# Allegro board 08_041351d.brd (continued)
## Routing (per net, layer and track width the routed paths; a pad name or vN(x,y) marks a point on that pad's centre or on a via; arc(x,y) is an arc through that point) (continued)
UNNAMED_10_RES_I39_N2: length 2.7
  TOP w0.14: v1(77.27,50.4) 77.27,51.04 Y4.1
  BOTTOM w0.14: R55.2 R54.2 77.14,50.53 v1(77.27,50.4)
UNNAMED_13_CN100PODDEVEN_I16_N4: length 6.8
  BOTTOM w0.089: JP3.2 16.31,31.52 16.18,31.64 14.78,31.64 14.4,32.02 14.4,32.49 14.28,32.62 14.28,33.81 14.03,34.06 13.57,34.06 13.29,33.77 JX3.58
UNNAMED_13_CN100PODDEVEN_I16_N5: length 6.8
  BOTTOM w0.089: JP4.2 16.31,31.99 16.18,31.86 14.87,31.86 14.62,32.11 14.62,32.58 14.49,32.71 14.49,33.9 14.12,34.27 13.51,34.27 13.21,34.57 JX3.60
UNNAMED_13_CN100PODDEVEN_I17_N4: length 4.9
  BOTTOM w0.089: JX3.57 7.32,33.77 7.04,34.06 6.85,34.06 6.22,33.42 4.79,33.42 4.62,33.25 JP1.2
UNNAMED_13_CN100PODDEVEN_I17_N5: length 4.8
  BOTTOM w0.089: JP2.2 4.62,33.76 4.75,33.64 6.13,33.64 6.76,34.27 7.04,34.27 7.34,34.57 JX3.59
USB_ID: length 24.4
  TOP w0.14: U15.23 v1(19.63,51.69)
  L6_SIGNAL w0.095: v1(19.63,51.69) 17.83,49.89 17.83,40.68 13.01,35.86 9.76,35.86 v1(9.45,36.17)
  BOTTOM w0.14: JX3.63 v1(9.45,36.17)
USB_OTG_CPEN: length 21.1
  TOP w0.14: U15.17 v1(19,54.69)
  L6_SIGNAL w0.095: v1(13.91,38.57) 13.91,39.37 16.63,42.08 16.63,52.31 v1(19,54.69)
  BOTTOM w0.14: JX3.70 v1(13.91,38.57)
USB_OTG_N: length 32.1
  TOP w0.089: 16.5,52.64 U16.6 ; 16.5,52.64 16.84,52.98 18.18,52.98 19.03,53.83 19.76,53.83 19.9,53.69 U15.19 ; 16.5,52.64 16.15,52.98 13.86,52.98 12.59,51.71 9.23,51.71 8.51,52.43 v1(8.31,52.43)
  L6_SIGNAL w0.089: v1(6.66,38.59) 6.91,38.34 7.55,38.34 8.69,39.48 8.69,51.67 8.82,51.8 8.82,52.18 8.56,52.43 v1(8.31,52.43)
  BOTTOM w0.089: v1(6.66,38.59) 6.95,38.3 7.13,38.3 7.4,38.57 JX3.69
USB_OTG_P: length 32.4
  TOP w0.089: 16.5,53.39 U16.1 ; 16.5,53.39 16.69,53.19 18.09,53.19 18.94,54.05 19.76,54.05 19.9,54.19 U15.18 ; 16.5,53.39 16.3,53.19 13.77,53.19 12.5,51.92 9.32,51.92 8.69,52.56 v1(8.69,52.81)
  L6_SIGNAL w0.089: v1(8.69,52.81) 8.69,52.66 9.07,52.28 9.07,51.69 8.94,51.57 8.94,39.37 7.65,38.08 v1(6.66,38.08)
  BOTTOM w0.089: JX3.67 7.35,37.77 7.04,38.08 v1(6.66,38.08)
USB_VBUS_OTG: length 19.8
  TOP w0.14: U15.22 19.11,52.19 v1(19.1,52.18)
  L6_SIGNAL w0.095: v1(19.1,52.18) 18.72,52.18 17.2,50.65 17.2,40.62 14.4,37.83 v1(13.9,37.83)
  BOTTOM w0.14: JX3.68 13.84,37.77 v1(13.9,37.83)
V_0_N: length 36
  TOP w0.127: U1.K9 v1(29.94,32.19)
  L16_SIGNAL w0.095: v1(29.94,32.19) 29.08,32.19 28.65,31.76 21.02,31.76 20.8,31.53 20.8,31.52 20.12,30.84 20.12,23.1 12.88,15.86 11.99,15.86 9.7,13.57 v1(9.7,12.17)
  BOTTOM w0.14: JX3.3 v1(9.7,12.17)
V_0_P: length 35
  TOP w0.127: U1.L10 v1(28.34,31.39)
  L16_SIGNAL w0.095: v1(10.59,11.37) 12.08,11.37 15.42,14.71 15.42,16.24 20.5,21.32 20.5,29.95 21.39,30.84 27.1,30.84 27.31,31.05 27.68,31.05 28.02,31.39 v1(28.34,31.39)
  BOTTOM w0.14: v1(10.59,11.37) JX3.1
VTT_0P75: length 21
  TOP w0.305: R150.2 v1(45.2,49.57)
  TOP w0.356: R148.2 v1(45.77,48.24) ; R159.2 v1(46.66,42.78) ; R138.2 v1(46.66,45.83) ; R146.2 45.19,48.99 45.2,49.13 v1(45.2,49.57) ; R156.2 v1(46.66,42.02) ; R149.2 v1(45.77,46.72) ; R143.2 v1(51.61,46.97) ; R140.2 v1(51.61,45.96) ; R152.2 v1(40.06,44.56) ; R145.2 v1(49.01,49.57) ; R155.2 v1(46.66,43.54) ; R137.2 v1(45.77,47.48) ; R162.2 v1(39.68,42.65) ; R144.2 v1(42.15,49.57) ; R154.2 R136.2 v1(46.66,45.07) ; R139.2 v1(40.06,45.45) ; R153.2 v1(51.61,45.07) ; R141.2 v1(40.06,46.34) ; R163.2 v1(40.18,43.54) ; R147.2 v1(51.23,44.05) ; R151.2 v1(47.49,49.57)
  TOP w0.406: R160.2 v1(51.36,40.62)
  BOTTOM w0.203: U14.3 48.52,59.42
  BOTTOM w0.305: U24.2 76.63,41.6 76.13,41.1 76.13,39.8
  BOTTOM w0.381: C101.1 52.25,47.61 v1(51.61,46.97)
  BOTTOM w0.508: v1(51.74,59.54) C80.1 50.6,59.54 50.47,59.67 v1(50.34,59.67) 50.22,59.67 50.09,59.54 R161.1
  BOTTOM w0.635: 76.13,39.8 v1(76.13,37.83) v1(76.71,37.83)
  vias: v1(49.58,57.26) v1(50.22,57.26) v1(51.61,57.26)
VTTVREF: length 133.5
  TOP w0.127: U1.H6 v1(31.54,34.59) ; U1.P6 v1(25.94,34.59)
  TOP w0.254: C123.2 48.76,27.56 v1(48.83,27.63) ; v1(46.79,44.3) 47.04,44.56 C122.2 ; C102.1 42.4,40.3 v1(42.43,40.33) ; C103.1 42.4,23.54 v1(42.43,23.57)
  TOP w0.508: v1(46.34,58.27) 46.03,58.59 C81.1
  L3_SIGNAL w0.254: v1(46.79,44.3) 45.9,44.3 45.26,43.67 45.26,41.76 44.63,41.13 42.72,41.13 42.43,40.83 v1(42.43,40.33)
  L6_SIGNAL w0.254: v1(74.35,37.55) 74.35,38.56 74.09,38.82 74.09,39.22 75.11,40.24 75.11,43.48 74.54,44.05 74.54,46.15 72.95,47.73 72.95,49.13 71.17,50.91 68,50.91 62.41,56.5 49.2,56.5 47.42,58.27 v1(46.34,58.27) 45.85,57.78 45.85,52.28 45.9,52.23 45.9,49.38 45.26,48.75 45.26,45.19 46.15,44.3 v1(46.79,44.3)
  L9_POWER w0.203: v1(31.54,34.59) 31.93,34.98 31.93,37.19 32.13,37.4 32.5,37.4 32.73,37.63 32.73,37.99 32.93,38.2 37.9,38.2
  L9_POWER w0.254: 37.9,38.2 37.91,38.21 39.17,38.21 41.29,40.33 v1(42.43,40.33)
  L15_SIGNAL w0.203: v1(31.54,34.59) 31.14,34.2 26.57,34.2 26.18,34.59 v1(25.94,34.59)
  L16_SIGNAL w0.254: v1(46.79,44.3) 46.41,44.3 46.03,43.92 46.03,41.76 46.41,41.38 46.41,28.81 47.42,27.79 48.66,27.79 v1(48.83,27.63) 48.36,27.16 47.8,27.16 47.17,26.52 47.17,25.76 46.03,24.62 43.99,24.62 43.74,24.87 42.85,24.87 42.43,24.45 v1(42.43,23.57)
  BOTTOM w0.178: 47.83,44.3 47.81,44.3 47.79,44.32 47.46,44.32 47.44,44.3 47.43,44.3
  BOTTOM w0.203: 47.43,44.3 v1(46.79,44.3) ; C84.1 v1(46.34,58.27) 46.34,58.41 46.14,58.62 U14.6 ; U2.H1 v1(42.43,23.57) ; U3.M8 48.26,44.1 48.19,44.1 47.98,44.3 47.83,44.3
  BOTTOM w0.254: v1(74.35,37.55) 75.31,38.51 75.31,41 76.13,41.82 U24.3 ; U2.M8 48.83,27.57 v1(48.83,27.63) ; U3.H1 v1(42.43,40.33)
  BOTTOM w0.305: v1(31.54,34.59) 31.66,34.46 C77.1 ; C76.1 26.06,34.46 v1(25.94,34.59)
XTAL_N: length 3.4
  TOP w0.127: U17.M12 69.6,34.75 v1(69.22,35.14)
  BOTTOM w0.14: v1(69.22,35.14) 70.18,35.14 C165.1 C216.2

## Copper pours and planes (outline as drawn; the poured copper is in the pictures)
1.0V on TOP: 36.37,12.94 36.37,15.22 37.64,15.22 37.64,14.01 38.15,14.01 38.15,12.94
1.0V on TOP: 12.37,7.22 12.37,0.49 9.45,0.49 9.45,7.22
1.0V on TOP: 57.08,1.25 56.57,1.76 56.57,2.14 57.08,2.65 57.08,5.19 58.47,5.19 58.47,1.25
1.0V on BOTTOM: 9.45,7.22 9.45,0.49 12.37,0.49 12.37,7.22
1.0V on BOTTOM: 56.31,1.38 56.31,5.19 58.47,5.19 58.47,1.38
1.0V on L3_SIGNAL: 57.08,5.95 57.08,11.41 37.39,11.41 36.63,12.17 36.63,12.81 35.99,13.44 35.99,14.46 63.3,14.46 64.31,13.44 64.31,5.32 59.36,0.36 9.32,0.36 9.32,7.35 14.78,7.35 16.69,5.44 27.48,5.44 28.25,4.68 33.33,4.68 34.6,3.41 36.12,3.41 36.37,3.66 52.12,3.66 52.38,3.41 54.54,3.41
1.8V on TOP: 58.98,12.3 60.89,12.3 60.89,13.32 60.38,13.32 60.38,15.35 58.6,15.35 57.33,14.21 56.44,14.21 56.44,12.05 55.68,11.41 55.68,11.03 57.71,11.03
1.8V on TOP: 78.03,5.32 77.14,6.2 77.14,6.97 76.63,7.47 76.63,8.49 76.89,8.74 77.65,8.74 77.65,7.47 78.41,6.71 81.33,6.71 81.71,6.33 81.71,5.44 81.46,5.19 80.57,5.19 80.19,4.81 80.19,2.9 79.94,2.65 78.54,2.65 78.03,3.16
1.8V on TOP: 28.75,5.44 28.75,4.3 30.53,4.3 30.53,5.44
1.8V on TOP: 11.74,11.54 11.74,10.65 15.29,10.65 15.29,12.05 15.04,12.3 15.04,13.32 13.51,13.32
1.8V on L9_POWER: 89.32,9.45 89.29,9.46 91.24,11.41 91.24,42.15 87.17,46.21 75.49,46.21 74.22,47.48 74.22,53.19 74.35,53.32 95.81,53.32 99.11,50.02 99.11,8.11 92.64,1.63 15.29,1.63 11.79,5.14 11.79,12.1 13.39,13.7 22.28,13.7 28.63,7.35 31.55,7.35 32.18,6.71 63.17,6.71 63.17,10.4 61.52,12.05 58.85,12.05 58.85,16.36 60,17.51 67.24,17.51 67.87,17 70.28,14.59 71.17,14.08 73.33,14.08 74.98,12.17 75.11,12.05 75.11,8.62 88.44,8.62 89.13,9.3 89.14,9.27 89.16,9.24 89.19,9.21 89.27,9.17 89.35,9.21 89.38,9.24 89.41,9.32 89.38,9.39 89.35,9.43 ; 15 cut-outs
1.35V on TOP: 62.79,16.11 62.79,13.95 66.73,13.95 66.73,16.11
1.35V on BOTTOM: 65.71,17.38 65.71,13.44 62.79,13.44 61.39,14.97 61.39,17.25 61.52,17.38
1.35V on L10_POWER: 50.85,1.51 50.85,4.81 51.49,5.44 52,5.44 52.25,5.19 52.25,3.54 52.88,2.9 57.08,2.9 58.73,4.55 58.73,15.86 60.12,17.25 64.31,17.25 66.22,15.35 66.22,12.43 64.44,10.65 62.92,10.65 61.65,9.38 61.65,2.65 59.74,0.74 51.61,0.74
3.3V on TOP: 37.64,53.32 35.8,53.32 35.42,53.7 35.42,56.43 36.56,56.43 36.56,55.1 36.95,54.72 37.64,54.72
3.3V on L10_POWER: 9.45,21.19 11.99,18.65 11.99,17.76 11.23,17 0.69,17 0.56,17.13 0.56,50.78 11.1,61.32 37.01,61.32 37.9,60.43 37.9,53.83 37.39,53.32 36.37,53.32 32.06,57.64 25.07,57.64 24.44,58.27 12.5,58.27 10.09,55.86 10.09,32.49 7.93,30.33 5.77,30.33 5.13,29.7 5.13,28.81 5.77,28.18 8.18,28.18 9.45,26.91
3.3V on L10_POWER: 70.41,61.2 70.41,42.4 78.16,42.4 81.59,45.83 81.59,61.2 ; 4 cut-outs
3.3V on L15_SIGNAL: 11.99,18.9 10.34,18.9 9.83,18.4 9.83,18.02 12.37,15.48 17.71,15.48 20.37,18.14 25.33,18.14 25.83,17.63 25.83,15.09 26.6,14.33 26.6,12.68 30.02,9.25 30.02,7.6 30.66,6.97 31.04,6.97 31.55,7.47 31.55,10.78 26.6,15.73 26.6,18.14 25.33,19.41 19.86,19.41 17.96,17.51 13.39,17.51
3.3V on L15_SIGNAL: 34.98,53.64 36.82,53.64 36.82,55.54 37.33,56.05 78.96,56.05 81.71,58.81 81.71,59.67 33.07,59.67 32.31,58.91 32.31,57.77 32.69,57.39 33.96,57.39 34.6,56.75 34.6,54.02
GND on TOP: 58.73,9.13 60.25,9.13 61.01,8.36 61.01,5.32 60.63,4.93 60.63,4.3 60.25,3.92 58.98,3.92 58.85,4.05 58.85,8.11 58.73,8.24
GND on TOP: 19.61,8.11 19.74,7.98 20.63,7.98 21.39,8.74 21.39,9 19.74,9 19.61,8.87
GND on TOP: 38.66,18.14 38.66,16.11 40.69,16.11 40.69,18.14
GND on TOP: 74.35,12.68 74.35,10.9 73.84,10.4 73.84,9.38 74.73,8.49 75.62,8.49 76.25,9.13 76.25,11.92 75.49,12.68
GND on TOP: 37.2,55.23 38.22,55.23 38.22,51.99 39.87,51.99 39.87,54.97 38.41,56.43 37.2,56.43
GND on TOP: 17.9,59.1 18.98,59.1 19.48,58.59 20.56,58.59 20.56,60.24 17.9,60.24
GND on TOP: 66.09,6.71 67.81,6.71 67.81,10.27 66.09,10.27
GND on TOP: outline of 104 points within 62.6,10.19 98.91,54.24 ; 21 cut-outs
GND on BOTTOM: 38.15,54.27 38.15,52.24 39.99,52.24 39.99,54.27
GND on BOTTOM: 60.38,24.62 60.38,30.59 61.14,30.59 61.14,31.35 61.71,31.35 61.71,32.24 61.46,32.24 61.46,34.02 60.38,34.02 60.38,34.53 66.92,34.53 66.92,34.21 67.55,34.21 67.55,34.53 70.16,34.53 70.16,24.62 ; 3 cut-outs
GND on BOTTOM: 66.16,7.86 67.43,7.86 67.43,9.7 66.35,9.7 66.16,9.51
GND on BOTTOM: 65.46,2.84 66.47,2.84 66.73,3.09 69.2,3.09 69.39,2.9 70.47,2.9 70.47,3.79 68.95,5.32 65.46,5.32
GND on BOTTOM: 60.69,24.05 60.69,19.48 60.76,19.41 59.55,19.41 59.55,23.86 59.74,24.05
GND on BOTTOM: 19.36,58.72 21.45,58.72 21.45,60.18 19.36,60.18
GND on BOTTOM: 83.49,24.43 83.81,24.11 83.81,22.97 84.82,22.97 84.82,26.71 84.76,26.78 84.38,26.78 83.49,25.89
GND on BOTTOM: 73.33,31.67 73.33,30.33 74.73,30.33 74.98,30.59 76.19,30.59 76.19,31.67
GND on L2_GROUND: 3.74,0.62 2.34,1 1.2,2.01 0.69,3.16 0.69,58.27 0.94,59.54 1.58,60.43 2.59,61.2 3.74,61.32 96.7,61.32 97.59,61.2 98.6,60.43 99.11,59.67 99.37,58.66 99.37,3.41 99.11,2.39 98.6,1.51 97.59,0.87 96.45,0.62 ; 15 cut-outs
GND on L3_SIGNAL: 89.84,10.27 85.65,14.46 69.55,14.46 69.55,17.81 66.17,17.81 63.68,20.3 63.68,23.73 65.2,25.25 65.2,25.76 65.61,26.17 68.89,26.17 68.89,31.6 68.38,32.11 68.38,34.22 67.92,34.22 67.74,34.4 67.74,44.61 80.06,44.61 85.78,50.32 85.78,54.24 98.68,54.24 98.91,54.01 98.91,10.65 98.53,10.27
GND on L5_GROUND, L14_GROUND, L17_GROUND: 3.74,0.62 2.34,1 1.2,2.01 0.69,3.16 0.69,58.27 0.94,59.54 1.58,60.43 2.59,61.2 3.74,61.32 96.7,61.32 97.59,61.2 98.6,60.43 99.11,59.67 99.37,58.66 99.37,3.41 99.11,2.39 98.6,1.51 97.59,0.87 96.45,0.62 ; 2 cut-outs
GND on L8_GROUND, L11_GROUND: 3.74,0.62 2.21,1 1.07,2.14 0.69,3.28 0.69,58.91 1.32,60.31 2.34,61.2 3.74,61.32 96.57,61.32 97.59,61.2 98.6,60.43 99.11,59.67 99.37,58.53 99.37,3.41 99.11,2.39 98.6,1.51 97.59,0.87 96.45,0.62 ; 2 cut-outs
VCC-1P35 on TOP: 52.91,57.66 52.91,59.65 52.48,60.08 47.6,60.08 47.6,61.5 55.07,61.5 55.07,57.66 ; 1 cut-out
VCC-1P35 on BOTTOM: 55.93,15.09 56.44,14.59 59.87,14.59 60.5,15.22 60.5,16.24 60.25,16.49 55.93,16.49
VCC-1P35 on BOTTOM: 47.55,61.45 47.55,60.18 48.44,60.18 48.44,61.45
VCC-1P35 on L9_POWER: 41.33,18.27 41.33,39.48 41.2,39.48 41.2,48.75 41.45,49 42.09,49 43.11,47.99 43.11,43.16 45.14,41.13 47.55,41.13 47.8,41.38 47.8,46.08 48.19,46.46 48.95,46.46 49.46,46.97 49.96,46.97 50.34,46.59 50.34,39.99 50.6,39.73 51.61,39.73 52.38,40.49 52.38,45.83 52.63,46.08 52.63,49.26 52.38,49.51 52.38,59.42 52.76,59.8 54.28,59.8 58.35,55.73 58.35,37.7 53.14,32.49 53.14,23.86 51.36,22.08 51.36,18.78 50.09,17.51 42.09,17.51
VCC-3P3V on TOP: 21.19,58.66 21.19,60.5 24.18,60.5 24.18,58.66
VCC-3P3V on L3_SIGNAL: 12.75,61.45 46.03,61.45 46.03,60.43 45.14,59.54 26.34,59.54 25.2,58.4 17.07,58.4 16.18,57.51 13.39,57.51 12.63,56.75 12.63,54.97 11.74,54.08 11.36,54.08 10.97,54.46 10.97,59.67
VCC-3P3V-IO on L9_POWER: 0.69,7.35 0.69,41 6.53,46.84 12.63,46.84 25.33,59.54 30.15,59.54 35.87,53.83 35.87,48.5 31.04,43.67 31.04,34.91 30.41,34.27 23.93,34.27 23.48,34.34 22.4,35.41 22.4,40.11 20.63,41.89 12.5,41.89 6.91,36.3 6.91,23.48 4.24,23.48 4.24,18.4 4.62,18.02 7.8,18.02 8.18,17.63 8.18,7.35
VCC-BRAM on BOTTOM: 54.41,4.3 54.41,0.87 55.42,0.87 55.42,4.55 54.66,4.55
VCC-BRAM on L9_POWER: 37.01,31.86 31.42,31.86 30.91,31.35 30.91,30.72 32.69,28.94 36.76,28.94 37.39,28.3 37.39,16.49 38.79,15.09 51.61,15.09 55.17,18.65 55.17,21.06 54.41,21.83 52.38,21.83 52,21.44 52,18.27 50.73,17 41.84,17 40.69,18.14 40.69,28.18
VCC-BRAM on L10_POWER: 54.41,3.28 54.41,6.33 55.3,7.22 55.3,10.01 54.54,10.78 53.39,10.78 53.39,21.19 56.69,21.19 58.35,19.54 58.35,4.93 56.69,3.28
VCC-BRAM on L16_SIGNAL: 54.22,3.41 55.11,3.41 55.55,3.85 55.55,4.68 54.54,5.7 54.47,5.7 54.03,5.25 54.03,3.6
VCCINT-1P0V on TOP: 25.33,14.97 25.33,19.16 26.34,19.16 27.99,20.81 29.52,20.81 29.52,19.41 27.87,19.41 27.61,19.16 27.61,17.51 37.64,17.51 37.64,15.98 29.9,15.98 29.9,14.97
VCCINT-1P0V on L9_POWER: 24.94,29.7 24.94,27.54 28.25,27.54 28.25,21.7 27.36,20.81 27.36,19.03 28.25,18.14 28.25,16.62 28.75,16.11 36.25,16.11 36.88,16.75 36.88,27.92 36.37,28.43 32.56,28.43 30.02,30.97 25.83,30.97
VCCO-DDR on TOP: 46.92,1.38 46.92,3.03 47.17,3.28 48.44,3.28 48.69,3.54 48.69,5.06 48.95,5.32 49.46,5.32 49.71,5.06 49.71,1.63 49.2,1.12 47.17,1.12
VCCO-DDR on L10_POWER: 50.09,29.06 48.44,34.4 42.98,36.05 38.79,36.05 37.9,35.16 35.99,35.16 35.61,34.78 23.04,34.78 20.75,37.07 20.75,40.11 22.79,42.15 23.29,42.15 23.67,41.76 23.67,41.38 24.06,41 25.33,41 25.58,41.26 25.58,41.89 25.83,42.15 26.09,42.15 26.34,41.89 26.34,41.38 26.72,41 30.28,41 31.68,42.4 35.1,42.4 35.49,42.02 35.49,41.38 35.74,41.13 36.5,41.13 36.88,41.64 36.88,42.15 37.14,42.4 54.66,42.4 54.66,23.35 52.88,21.57 52.88,10.78 52.25,10.14 52.25,6.84 50.47,5.06 50.47,4.3 49.96,3.79 49.2,3.79 49.2,8.74 50.09,9.89
VCCPCOM-1P8V on TOP: 17.93,58.59 18.91,58.59 19.31,58.2 23.9,58.2 24.08,58.02 24.08,56.42 23.83,56.17 23.8,56.01 23.52,56.01 23.5,56.12 23.14,56.47 22.73,56.47 22.38,56.12 22.3,56.01 21.87,56.01 20.82,57.07 18.45,57.07 17.93,57.59
VCCPCOM-1P8V on TOP: 25.07,55.61 25.07,54.85 25.33,54.59 25.83,54.59 26.34,55.1 26.34,55.99 26.21,56.12 25.58,56.12
VCCPCOM-1P8V on TOP: 14.53,38.08 14.53,35.48 18.21,35.48 18.21,38.08
VCCPCOM-1P8V on BOTTOM: 16.56,17.76 14.4,17.76 14.02,17.38 14.02,15.73 14.28,15.48 14.66,15.48 15.17,15.98 15.17,16.49 15.29,16.62 16.44,16.62 16.56,16.75
VCCPCOM-1P8V on BOTTOM: 61.14,43.8 61.14,48.62 62.66,48.62 62.66,46.59 63.68,46.59 63.68,43.8
VCCPCOM-1P8V on L10_POWER: 65.9,42.84 37.45,42.84 36.76,42.15 36.76,41.76 36.37,41.38 36.12,41.38 35.87,41.64 35.87,42.27 35.36,42.78 31.29,42.78 30.02,41.38 27.1,41.38 26.72,41.76 26.72,42.15 26.34,42.53 25.58,42.53 25.33,42.27 25.33,41.51 25.2,41.38 24.31,41.38 24.06,41.64 24.06,42.02 23.55,42.53 22.53,42.53 20.25,40.24 20.25,36.81 22.79,34.27 35.74,34.27 36.25,34.78 37.01,34.78 38.91,32.87 38.91,31.6 39.93,30.59 43.36,30.59 44.38,29.57 44.38,14.08 45.01,13.44 45.01,9 45.52,8.49 47.93,8.49 48.69,7.73 48.69,2.52 48.19,2.01 9.96,2.01 6.78,1.89 1.45,7.22 1.45,16.11 11.23,16.11 12.5,17.38 12.5,18.9 9.96,21.44 9.96,24.11 10.09,24.24 10.09,25.51 9.96,25.64 9.96,27.03 8.31,28.68 6.02,28.68 5.64,29.06 5.64,29.45 6.02,29.83 8.31,29.83 10.85,32.37 10.85,55.86 12.75,57.77 24.18,57.77 25.07,56.88 31.8,56.88 35.74,52.94 37.64,52.94 43.49,58.78 47.8,58.78 50.47,61.45 69.52,61.45 69.78,61.2 69.78,46.72 ; 8 cut-outs
VCCPINT-1P0V on TOP: 55.68,8.36 55.68,6.46 56.69,6.46 57.2,5.95 57.96,5.95 58.35,6.33 58.35,7.35 57.96,7.73 57.96,8.36
VCCPINT-1P0V on L9_POWER: 24.94,34.02 30.91,34.02 33.07,36.18 39.68,36.18 40.57,35.29 40.57,31.86 40.06,31.35 38.28,31.35 37.39,32.24 31.29,32.24 30.41,31.35 26.21,31.35 25.33,32.24 25.33,32.75 24.56,33.51 24.56,33.64
VCCPINT-1P0V on L9_POWER: 45.26,10.01 45.26,7.22 58.09,7.22 58.09,8.24 56.31,10.01 ; 1 cut-out
VCCPINT-1P0V on L10_POWER: 42.85,35.67 39.04,35.67 38.41,35.03 38.41,34.27 39.3,33.38 39.3,31.86 40.18,30.97 43.61,30.97 44.76,29.83 44.76,14.33 45.39,13.7 45.39,9.38 45.77,9 48.31,9 49.71,10.4 49.71,28.68 48.06,34.02
VCCPINT-1P0V on L12_SIGNAL: 55.68,9.63 57.84,9.63 58.73,10.52 76.38,10.52 79.3,7.6 79.3,3.28 78.03,2.01 67.36,2.01 63.3,6.08 56.19,6.08 55.04,7.22 55.04,9 ; 4 cut-outs
VDD_INTERFACE on BOTTOM: 61.08,21.32 61.08,23.98 61.14,24.05 62.09,24.05 62.03,23.98 62.03,21.19 62.41,20.81 62.41,19.48 61.27,19.48 61.27,21.13
VDD_INTERFACE on L10_POWER: 71.17,17.89 59.87,17.89 58.98,18.78 58.98,19.54 56.82,21.7 56.06,21.7 55.55,22.21 55.55,30.21 57.96,30.21 58.73,29.45 61.39,29.45 62.41,30.46 62.41,31.86 63.68,33.13 63.68,34.91 63.93,35.16 67.36,35.16 67.36,32.62 66.22,31.48 66.22,28.18 65.46,27.41 62.79,27.41 62.54,27.16 62.54,22.46 63.81,21.19 66.73,21.19 67.74,20.17 73.97,20.17 74.73,19.41 74.73,12.68 76.38,11.03 76.38,8.74 77.4,7.73 81.84,7.73 82.35,8.24 85.65,8.24 85.65,3.16 77.78,3.16 71.43,9.51 71.43,17.63
VDD_INTERFACE on L12_SIGNAL: 34.67,24.8 34.67,24.85 35.61,23.98 35.61,23.48 35.74,23.35 35.74,23.1 35.49,22.84 34.09,22.84 32.82,24.11 32.82,25.13 32.59,25.36 32.59,25.74 32.11,25.74 32.11,25.31 31.68,24.87 31.68,21.95 32.69,20.94 34.72,20.94 38.79,16.87 40.44,16.87 41.33,15.98 44.25,15.98 44.76,16.49 49.58,16.49 56.69,23.6 61.65,23.6 62.54,22.71 62.54,21.95 58.65,18.07 54.84,18.07 51.74,14.97 43.11,14.97 41.33,13.19 39.3,13.19 36.88,15.6 36.5,15.6 33.83,18.27 31.42,18.27 29.14,20.56 29.14,23.1 27.1,25.13 27.1,26.52 28.12,27.54 31.8,27.54 33,26.45 33,25.64 33.73,25.64 33.73,25.74 33.86,25.61 33.86,24.8
VDDA_GPO on L10_POWER: 79.05,41.76 82.35,45.07 82.35,61.2 88.32,61.2 88.32,39.22 85.14,36.05 73.08,36.05 71.43,37.7 61.52,37.7 59.49,35.67 59.49,32.37 59.87,31.99 60.5,31.99 60.89,31.6 61.52,31.6 61.52,30.33 61.14,29.95 58.73,29.95 57.96,30.72 56.06,30.72 55.68,31.1 55.68,37.19 60.25,41.76 ; 3 cut-outs
1P3_SUPPLY_A on L10_POWER: 77.9,8.11 76.89,9.13 76.89,11.28 75.49,12.68 75.49,19.54 74.47,20.56 70.36,20.56 70.36,21.37 69.55,21.37 69.55,20.56 68.25,20.56 67.24,21.57 64.02,21.57 62.87,22.72 62.79,27.03 65.58,27.03 66.73,28.18 66.73,31.22 67.74,32.11 67.74,35.41 67.49,35.67 63.81,35.67 62.66,34.53 62.66,32.62 62.03,31.99 61.01,31.99 60.5,32.49 60.5,35.67 61.9,37.07 71.3,37.07 81.92,26.45 81.92,10.12 78.92,10.12 78.92,8.11
1P3_SUPPLY_B on BOTTOM: 73.33,29.95 73.33,29.13 74.66,29.13 74.86,28.87 76.13,28.87 76.13,29.95
1P3_SUPPLY_B on BOTTOM: 65.71,36.62 67.81,36.62 67.81,38.14 67.17,38.14 66.66,38.65 65.71,38.65
1P3_SUPPLY_B on L9_POWER: 67.87,22.08 69.78,23.98 69.78,35.62 66.42,35.62 64.95,37.09 64.95,38.21 63.81,39.35 59.74,39.35 59.62,39.48 59.62,43.42 59.87,43.67 69.78,43.67 74.86,38.59 74.86,36.68 79.3,36.68 79.3,45.57 85.9,45.57 90.73,40.75 90.73,11.79 88.19,9.25 85.78,9.25 84.89,10.14 75.62,10.14 75.62,14.84 72.44,14.84 72.44,14.97 69.39,18.14 63.17,18.14 62.28,19.03 62.28,22.08 ; 4 cut-outs
ADP2114_VIN on L16_SIGNAL: 60.76,4.55 60.76,0.74 73.2,0.74 73.2,4.55 ; 1 cut-out
JX_VCCO_13 on BOTTOM: 18.09,41.64 18.09,39.22 20.63,39.22 20.63,41.64
JX_VCCO_13 on L9_POWER: 7.55,22.97 7.55,35.92 12.88,41.26 20.37,41.26 22.02,39.61 22.02,34.27 23.04,33.26 24.31,33.26 24.82,32.75 24.82,30.72 24.44,30.72 24.44,28.81 19.99,28.81 19.99,26.14 18.09,26.14 17.58,25.64 17.58,19.67 16.44,18.52 5.01,18.52 4.75,18.78 4.75,22.97
JX_VCCO_34 on L9_POWER: 32.18,7.35 28.75,10.78 25.71,10.78 24.06,12.43 24.06,12.81 22.66,14.21 22.53,14.21 18.21,18.52 18.21,25.51 20.37,25.51 20.37,28.3 24.56,28.3 24.56,27.29 24.69,27.16 27.74,27.16 27.74,21.95 26.98,21.19 26.98,18.52 27.74,17.76 27.74,16.24 28.63,15.35 36.76,15.35 37.64,14.46 51.61,14.46 55.55,18.4 55.55,21.32 53.77,23.1 53.77,31.1 58.35,31.1 58.35,11.54 61.39,11.54 62.66,10.27 62.66,7.22 59.87,7.22 56.57,10.52 44.12,10.52 40.95,7.35 ; 1 cut-out
JX_VIN on TOP: 32.06,4.05 32.06,4.3 31.04,4.3 31.04,5.32 34.09,5.32 34.09,4.55 34.85,4.55 35.1,4.81 35.61,4.81 35.61,4.17 35.49,4.05
JX_VIN on TOP: 39.73,57.31 39.73,55.58 40.21,55.1 40.21,53.93 40.31,53.83 41.3,53.83 41.51,54.03 41.51,55.38 41.17,55.71 41.17,56.95 40.95,58.02 40.06,58.02
JX_VIN on TOP: 62.03,7.09 62.54,8.24 64.57,8.24 64.82,6.59 64.82,5.44 64.76,5.38 62.03,5.38
JX_VIN on TOP: 54.15,9 54.54,9.38 54.54,9.76 54.15,10.14 53.77,10.14 52.12,8.49 52.12,4.05 53.01,3.16 53.9,3.16 54.15,3.41
JX_VIN on TOP: 69.01,5.32 69.01,6.59 69.27,6.59 70.16,7.47 70.54,7.98 71.81,7.98 71.81,5.32
JX_VIN on BOTTOM: 52.12,5.32 52.12,3.28 52.25,3.16 53.9,3.16 54.03,3.28 54.03,4.55 54.54,5.06 54.54,5.44 53.39,5.44 53.27,5.32
JX_VIN on L3_SIGNAL: 34.85,3.79 33.58,5.06 18.21,5.06 15.42,7.86 14.91,7.86 14.91,8.62 11.1,8.62 9.83,9.89 10.09,9.89 10.09,10.65 9.96,10.65 9.96,10.9 9.32,10.9 9.32,18.65 11.1,20.43 11.1,48.75 19.1,56.75 25.33,56.75 26.47,57.89 46.53,57.89 48.31,59.67 54.03,59.67 55.17,58.53 55.17,49.89 54.03,48.75 49.84,48.75 49.46,49.13 41.96,49.13 40.06,51.04 28.88,51.04 24.69,46.84 21.13,46.84 17.32,43.03 17.32,16.11 20.88,12.55 29.01,12.55 29.9,11.67 35.61,11.67 36.5,10.78 56.31,10.78 56.31,6.2 53.9,3.79 52.63,3.79 52.25,4.17 36.12,4.17 35.74,3.79 ; 3 cut-outs
JX_VIN on L10_POWER: 62.28,9.13 62.28,0.62 75.49,0.62 76,1.12 76,4.05 69.9,10.14 63.3,10.14 ; 7 cut-outs
JX_VIN on L10_POWER: 52.63,3.92 53.9,3.92 53.9,6.46 54.92,7.47 54.92,9.76 54.41,10.27 53.14,10.27 52.63,9.76
JX_VIN on L13_SIGNAL: 53.65,5.44 55.93,7.73 61.39,7.73 61.9,7.47 62.41,7.73 63.43,8.74 71.55,8.74 73.97,6.33 75.36,6.33 75.36,0.74 71.55,0.74 31.29,0.87 30.79,1.38 30.79,6.33 32.18,6.33 33.07,5.44 ; 3 cut-outs
JX_VIN on L15_SIGNAL: 52.38,3.28 68.51,3.28 70.41,5.19 70.54,4.93 71.93,4.93 72.44,5.44 72.44,7.35 71.43,8.36 69.01,8.36 68,7.35 66.09,7.35 64.19,10.14 53.52,10.14 53.01,9.63 53.01,7.86 52.38,7.22 ; 2 cut-outs
PG_1P0V on L12_SIGNAL: 47.55,5.57 62.79,5.57 63.3,5.06 63.3,3.79 60.12,0.62 26.47,0.62 24.06,3.03 24.06,4.93 26.34,7.22 28.25,7.22 30.66,4.81 46.79,4.81
PHY1_1V8 on BOTTOM: 18.15,0.3 20.31,0.3 20.31,2.33 18.15,2.33
PHY1_1V8 on L13_SIGNAL: 15.8,8.24 15.8,3.03 14.66,1.89 14.66,1 14.91,0.74 30.28,0.74 30.28,4.36 29.45,5.19 29.45,6.14 27.36,8.24 ; 1 cut-out
PHY1_AVDD_1V8 on L15_SIGNAL: 15.42,14.84 19.36,14.84 22.28,17.76 24.82,17.76 25.45,17.13 25.45,15.98 23.8,14.33 23.8,11.92 21.77,9.89 21.77,3.28 21.01,2.52 18.72,2.52 15.42,5.82
PHY1_AVDD_3V3 on L13_SIGNAL: 15.29,8.74 15.29,10.01 16.94,11.67 16.94,15.73 14.15,18.52 14.15,20.81 18.09,20.81 18.09,18.02 23.29,12.81 24.94,12.81 25.2,12.55 25.2,11.28 23.8,9.89 19.86,9.89 18.72,8.74
PHY1_VDD_3V3 on L7_SIGNAL: 14.28,13.06 14.28,5.06 21.77,5.06 21.9,5.19 21.9,7.47 23.29,7.47 23.67,7.09 23.67,5.06 31.55,5.06 31.55,9.76 29.52,11.79 23.04,11.79 21.77,13.06
SYNC on TOP: 18.21,7.73 19.1,7.73 19.36,7.47 20.25,7.47 20.25,5.82 20.12,5.7 18.34,5.7 18.21,5.82
UNNAMED_9_ADP2114_I1272_SW1 on TOP: 65.08,6.71 65.84,6.71 65.84,12.3 64.19,12.3 64.19,8.74 64.95,8.62
UNNAMED_9_ADP2114_I1272_SW3 on TOP: 68.12,6.71 68.76,6.71 70.6,8.55 71.36,8.55 71.36,10.01 68.38,10.01 68.25,9.89 68.25,7.73 68.12,7.6
UNNAMED_9_CAP_I1364_N1 on TOP: 62.92,12.3 62.92,9.13 62.66,8.87 61.52,8.87 60.5,9.89 58.73,9.89 58.12,9.38 55.42,9.38 55.42,10.52 57.84,10.52 58.35,11.03 60.38,11.03 61.65,12.3
UNNAMED_9_CAP_I1394_N1 on TOP: 14.15,7.86 13.51,7.22 13.51,3.54 14.15,2.9 16.56,2.9 16.82,3.16 16.82,7.86 15.8,7.86 15.55,8.11 15.55,10.27 14.02,10.27 14.02,8.87 14.28,8.87 14.66,8.49 14.66,8.11 14.4,7.86
UNNAMED_9_CAP_I1401_N1 on TOP: 67.36,15.54 69.14,15.54 69.14,14.08 69.65,13.57 71.81,13.57 72.63,12.74 73.59,12.74 73.59,11.03 68.25,11.03 67.36,11.92
UNNAMED_10_ADM7160_I65_VOUT on TOP: 73.46,49.13 73.46,51.49 73.97,51.49 73.97,52.05 76.13,52.05 76.13,49.13
UNNAMED_10_ADM7160_I65_VOUT on BOTTOM: 76,52.43 76,51.42 75.01,51.42 74.63,51.04 73.84,51.04 73.84,51.92 74.09,52.18 75.74,52.18
VTT_0P75 on TOP: 50.8,57.66 52.27,57.66 52.27,59.85 50.14,59.85 50.14,59.49 50.8,58.96
VTT_0P75 on BOTTOM: 47.83,59.49 48.16,59.49 48.19,59.52 48.97,59.82 49.23,60 52.02,60 52.76,59.16 52.76,56.88 52.5,56.62 49.2,56.62 49.2,57.64 51.61,57.64 51.61,59.16 48.62,59.11 48.24,59.32 47.83,59.32
VTT_0P75 on L9_POWER: 51.87,59.42 51.87,49.38 52.25,49 52.25,46.46 51.87,46.08 51.87,40.49 51.49,40.11 50.85,40.11 50.73,40.24 50.73,46.84 50.22,47.35 47.93,47.35 47.42,46.84 47.42,42.02 47.04,41.64 45.52,41.64 43.61,43.54 43.61,48.24 42.47,49.38 41.2,49.38 40.82,49 40.82,42.4 40.31,41.89 39.42,41.89 37.77,43.54 37.77,58.15 41.07,61.45 70.16,61.45 73.59,58.02 73.59,46.84 74.86,45.57 78.67,45.57 78.67,37.95 78.03,37.32 75.49,37.32 75.49,39.22 70.41,44.3 58.98,44.3 58.98,55.73 54.54,60.18 52.63,60.18 ; 4 cut-outs

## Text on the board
BOTTOM: ADRV9364-Z7020
Ref Des/Silkscreen Bottom: 041351 REV D | PicoZed SDR 7020/AD9364
User.Comments: ASSEMBLY
Ref Des/Silkscreen Top: SDS | SDC | CFG DONE | PGOOD | 0 | 1 | JTAG  S4 0 S3 0 | QSPI  S4 1 S3 0 | SD   S4 1 S3 1
PAGE_OUTLINE: A | B | C | INITIAL RELEASE | AS PER ECR-061220 | AS PER ECR-067075 | 10FEB17 | N.W. | EVAL BOARD Z | 02-041351
DIMENSION: +2/-0 MILS | DIA MAX | SEE NOTE 15 | " " | REF | 4 PLACES
User.8: L2 GROUND | 08-      -07
User.9: L3 SIGNAL | 08-      -08
User.11: L4 SIGNAL | 08-      -09
User.12: L5 GROUND | 08-      -10
User.14: L6 SIGNAL | 08-      -11
User.15: L7 SIGNAL | 08-      -12
User.16: L8 GROUND | 08-      -13
User.17: L9 POWER | 08-      -14
User.18: INTERNAL SIGNAL (LAYER 12) | INTERNAL SIGNAL (LAYER 13) | GROUND PLANE    (LAYER 14) | INTERNAL SIGNAL (LAYER 15) | INTERNAL SIGNAL (LAYER 16) | GROUND PLANE    (LAYER 17) | LAYER | L1 | L3 | L4 | L6 | L7 | L12 | L13 | L15 | L16 | L18 | IMPEDANCE | 100 OHMS | 50 OHMS | 40 OHMS | 80 OHMS | ALL IMPEDANCES +/-10% | REFERENCE | L5/L2 | L5/L8 | L11/L14 | L14/L17 | L2 | LINE WIDTH | 15.5MILS | 10.5MILS | 3.5MILS | 7.75MILS | 3.75MILS | 5.5MILS | 5.1MILS | 6MILS | 10MILS | 6.5MILS | SPACE | 5MILS | N/A | 16.    BOARDS TO BE PANELIZED AND SHIPPED INTACT | IMPEDANCE TABLE
User.24: L10 POWER | 08-      -15
User.25: L11 GROUND | 08-      -16
User.26: L12 SIGNAL | 08-      -17
User.27: L13 SIGNAL | 08-      -18
User.28: L14 GROUND | 08-      -19
User.29: L15 SIGNAL | 08-      -20
User.30: L16 SIGNAL | 08-      -21
User.31: L17 GROUND | 08-      -22
User.35: 1. PINS 1 AND 2 OF JP1, JP2, JP3 AND JP4 SHOULD BE SHORTED BY THE ASSEMBLY | VENDOR BY APPLYING A SOLDER BLOB ACROSS THE PINS. | ASSEMBLY NOTES:
User.36: SECONDARY SIDE
User.45: 3 | 4 | 2 | FIGURE | SIZE | 8.0 | 10.0 | 45.0 | 31.0 | 47.0 | 155.0 | PLATED | NON-PLATED | FINISHED HOLES IN MILS | ALL UNITS ARE IN MILS | QTY | 1838 | 410 | 1 | TOLERANCE/NOTES | DRILLED HOLES LAYER 1 TO LAYER 2 | DRILLED HOLES LAYER 18 TO LAYER 17 | DRILLED HOLES LAYER 19 TO LAYER 20
